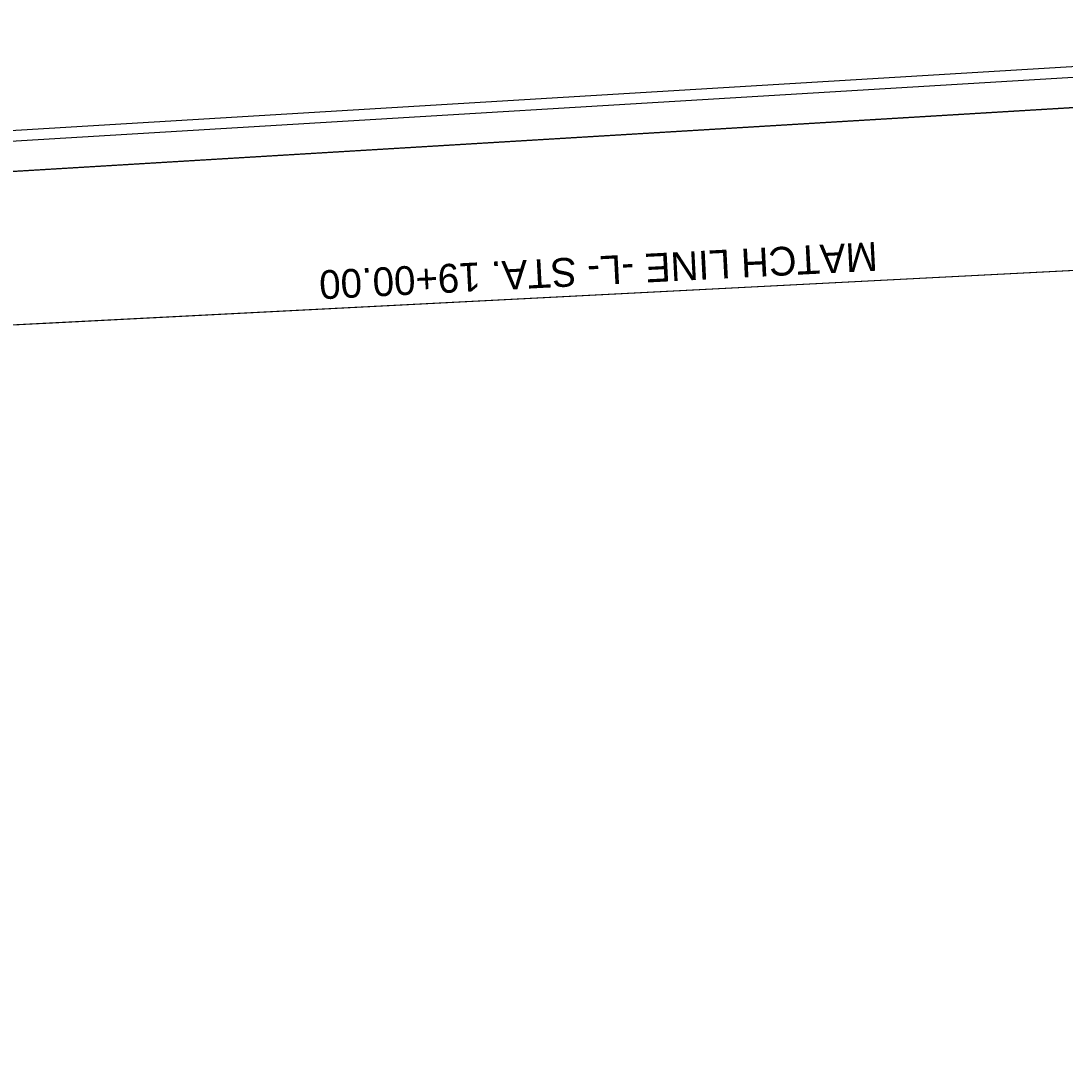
# Model space of a CAD drawing. Extents: x 2368361 to 2369555, y 800599 to 802345.
# Drawn here: x 2368697.7 to 2369133.3, y 801908.8 to 802345.4 of the extents above; entities that cross this region are included whole.
import ezdxf

# ---------------------------------------------------------------- set-up
doc = ezdxf.new("R2010")
doc.units = 0
for name, color, linetype in [('Default', 7, 'Continuous'), ('Old_Level_10', 7, 'Continuous'), ('Old_Level_2', 7, 'Continuous'), ('Old_Level_4', 7, 'Continuous'), ('Old_Level_6', 7, 'Continuous'), ('Old_Level_63', 7, 'Continuous'), ('Plot Shape CELL', 7, 'Continuous')]:
    doc.layers.add(name, color=color, linetype=linetype)

msp = doc.modelspace()

# ---------------------------------------------------------------- linework, layer by layer
at = {"layer": 'Default'}
msp.add_line((2368599.6, 802213.8), (2369436.2, 802256.78), dxfattribs=at)
at = {"layer": 'Old_Level_10'}
msp.add_lwpolyline([(2368474.82, 800766.64), (2369522.9, 800829.72), (2369432.81, 802327.02), (2368595.82, 802276.66), (2368610.18, 802037.84), (2368399.08, 802025.14)], close=True, dxfattribs=at)
at = {"layer": 'Old_Level_2'}
msp.add_lwpolyline([(2368470.23, 800828.51), (2368399.08, 802025.14), (2368610.18, 802037.84), (2368599.6, 802213.8), (2369302.23, 802249.9), (2369298.05, 802318.92), (2369432.81, 802327.03), (2369518.34, 800891.57)], close=True, dxfattribs=at)
msp.add_lwpolyline([(2368470.23, 800828.51), (2368399.08, 802025.14), (2368610.18, 802037.84), (2368599.6, 802213.8), (2369302.23, 802249.9), (2369298.05, 802318.92), (2369432.81, 802327.03), (2369518.34, 800891.57)], close=True, dxfattribs=at)
at = {"layer": 'Old_Level_4'}
msp.add_lwpolyline([(2369534.62, 800676.67), (2369434.56, 802339.65), (2368381.48, 802276.3), (2368481.53, 800613.31)], close=True, dxfattribs=at)
at = {"layer": 'Old_Level_6'}
msp.add_lwpolyline([(2369555.37, 800664.89), (2369454.26, 802345.35), (2368361.24, 802279.59), (2368462.34, 800599.13)], close=True, dxfattribs=at)
at = {"layer": 'Old_Level_63'}
msp.add_line((2368705.47, 802219.24), (2369121.34, 802240.6), dxfattribs=at)
at = {"layer": 'Plot Shape CELL'}
for points in [[(2368384.71, 802264), (2368474.79, 800766.67), (2369522.9, 800829.72), (2369432.81, 802327.03)], [(2369522.9, 800829.72), (2368474.82, 800766.64), (2368396.71, 802064.28), (2368546.5, 802073.31), (2368534.5, 802272.98), (2369432.81, 802327.03)]]:
    msp.add_lwpolyline(points, close=True, dxfattribs=at)

# ---------------------------------------------------------------- texts
at = {"layer": 'Old_Level_63'}
msp.add_text('MATCH LINE -L- STA. 19+00.00', height=12, rotation=182.9405, dxfattribs=at).set_placement((2369054.77, 802253.24))

doc.saveas('drawing.dxf')
